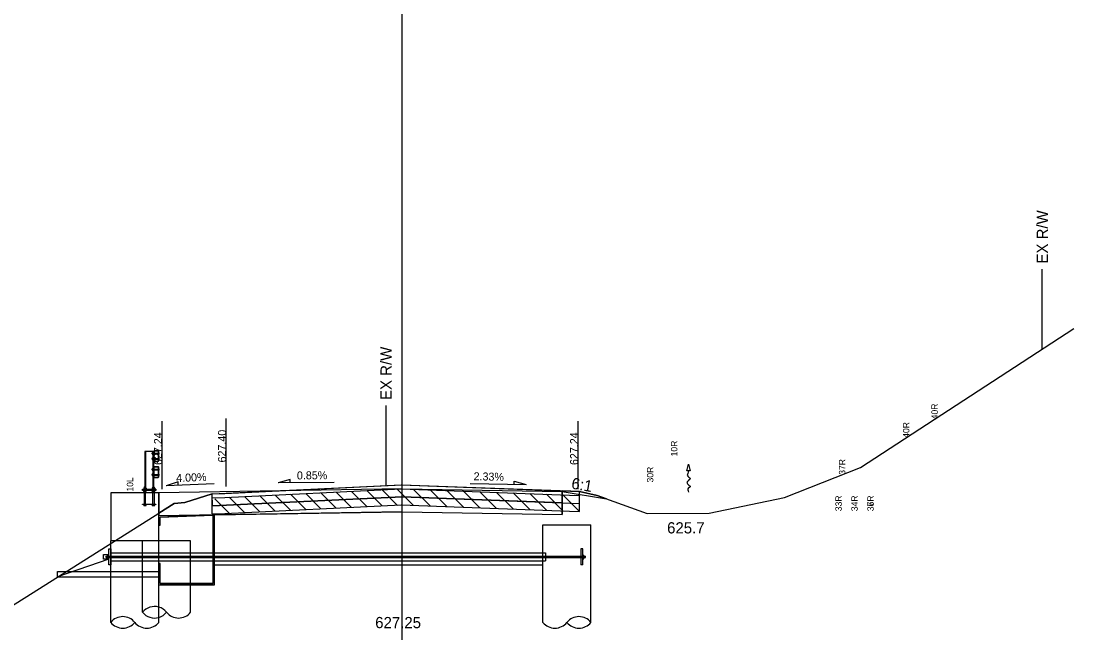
# Model space of a CAD drawing. Extents: x 1866342 to 1870084, y 421982 to 426629.
# Drawn here: x 1866444.3 to 1866510.1, y 426516.9 to 426555.1 of the extents above; entities that cross this region are included whole.
import ezdxf

# ---------------------------------------------------------------- set-up
doc = ezdxf.new("R2010")
doc.units = 0
for name, color, linetype in [('BR_P_Det_Object', 7, 'Continuous'), ('BR_P_Drain_Object', 7, 'Continuous'), ('BR_P_Gen_Hatch', 7, 'Continuous'), ('BR_P_Gen_Porous_Backfill', 7, 'Continuous'), ('BR_P_Sub_Deep_Hidden', 7, 'Continuous'), ('BR_P_Sub_Deep_Object', 7, 'Continuous'), ('BR_P_Sub_Object', 7, 'Continuous'), ('DR_P_Flow_Arrow', 7, 'Continuous'), ('GK_Cells', 7, 'Continuous'), ('RW_X_Fee_RW', 7, 'Continuous'), ('ST_Details', 7, 'Continuous'), ('XS_P_Annotation', 7, 'Continuous'), ('XS_P_Earthwork_Shapes', 7, 'Continuous'), ('XS_P_Finished_Grade', 7, 'Continuous'), ('XS_P_Pavt_Surface', 7, 'Continuous'), ('XS_P_Subgrade', 7, 'Continuous'), ('XS_P_Text_Info', 7, 'Continuous'), ('XS_P_Text_MarkedPoint', 7, 'Continuous'), ('XS_X_Ground_Line', 7, 'Continuous'), ('XS_X_Pavt', 7, 'Continuous')]:
    doc.layers.add(name, color=color, linetype=linetype)

msp = doc.modelspace()

# ---------------------------------------------------------------- linework, layer by layer
at = {"layer": 'BR_P_Det_Object'}
for p, q in [((1866449.46, 426521.491), (1866449.46, 426521.789)), ((1866449.46, 426521.789), (1866449.794, 426521.789)), ((1866449.794, 426521.141), (1866449.794, 426522.141)), ((1866449.794, 426522.141), (1866449.919, 426522.141)), ((1866449.919, 426522.141), (1866449.919, 426521.141)), ((1866449.919, 426521.891), (1866452.919, 426521.891)), ((1866479.294, 426522.141), (1866479.294, 426521.141)), ((1866479.419, 426522.141), (1866479.294, 426522.141)), ((1866479.419, 426521.141), (1866479.419, 426522.141)), ((1866449.794, 426521.491), (1866449.46, 426521.491)), ((1866449.627, 426521.683), (1866479.585, 426521.683)), ((1866449.627, 426521.6), (1866449.627, 426521.683)), ((1866449.627, 426521.6), (1866479.585, 426521.6)), ((1866449.794, 426521.735), (1866449.73, 426521.735)), ((1866449.73, 426521.547), (1866449.73, 426521.735)), ((1866449.794, 426521.547), (1866449.73, 426521.547)), ((1866449.919, 426521.141), (1866449.794, 426521.141)), ((1866449.919, 426521.391), (1866452.919, 426521.391)), ((1866479.419, 426521.141), (1866479.294, 426521.141)), ((1866479.419, 426521.756), (1866479.482, 426521.756)), ((1866479.419, 426521.526), (1866479.482, 426521.526)), ((1866479.482, 426521.526), (1866479.482, 426521.756)), ((1866479.585, 426521.6), (1866479.585, 426521.683))]:
    msp.add_line(p, q, dxfattribs=at)
at = {"layer": 'BR_P_Drain_Object'}
for p, q in [((1866452.919, 426521.891), (1866477.085, 426521.891)), ((1866477.085, 426521.891), (1866477.085, 426521.391)), ((1866452.919, 426521.391), (1866477.085, 426521.391)), ((1866446.597, 426520.725), (1866452.919, 426520.725)), ((1866446.597, 426520.391), (1866446.597, 426520.725)), ((1866446.597, 426520.391), (1866452.919, 426520.391))]:
    msp.add_line(p, q, dxfattribs=at)
at = {"layer": 'BR_P_Gen_Hatch'}
msp.add_lwpolyline([(1866452.919, 426523.624), (1866453.002, 426523.624), (1866453.002, 426524.124), (1866456.319, 426524.247), (1866456.319, 426519.975), (1866453.002, 426519.975), (1866453.002, 426521.225), (1866452.919, 426521.225)], close=True, dxfattribs=at)
at = {"layer": 'BR_P_Gen_Porous_Backfill'}
for p, q in [((1866453.002, 426524.124), (1866455.919, 426524.24)), ((1866453.002, 426523.624), (1866453.002, 426524.124)), ((1866456.319, 426524.247), (1866455.919, 426524.24)), ((1866456.319, 426519.975), (1866456.319, 426524.247)), ((1866453.002, 426523.624), (1866452.919, 426523.624)), ((1866453.002, 426521.225), (1866452.919, 426521.225)), ((1866453.002, 426519.975), (1866453.002, 426521.225)), ((1866453.002, 426519.975), (1866456.319, 426519.975))]:
    msp.add_line(p, q, dxfattribs=at)
at = {"layer": 'BR_P_Sub_Deep_Hidden'}
msp.add_line((1866454.903, 426522.641), (1866452.919, 426522.641), dxfattribs=at)
for points in [[(1866451.903, 426518.178), (1866451.903, 426522.641)], [(1866454.903, 426519.891), (1866454.903, 426522.641)]]:
    msp.add_lwpolyline(points, dxfattribs=at)
for centre, major_axis, start_param, end_param in [((1866452.653, 426517.575), (0.908, 0.32), 0.952163, 2.125879), ((1866452.653, 426518.781), (0.908, -0.32), 4.157306, 5.331022)]:
    msp.add_ellipse(centre, major_axis=major_axis, ratio=0.999997, start_param=start_param, end_param=end_param, dxfattribs=at)
at = {"layer": 'BR_P_Sub_Deep_Object'}
msp.add_line((1866476.919, 426523.641), (1866479.919, 426523.641), dxfattribs=at)
for points in [[(1866476.919, 426517.545), (1866476.919, 426523.641)], [(1866479.919, 426517.545), (1866479.919, 426523.641)], [(1866449.919, 426517.545), (1866449.919, 426522.641)], [(1866452.919, 426517.545), (1866452.919, 426522.641)], [(1866454.903, 426518.178), (1866454.903, 426519.891)]]:
    msp.add_lwpolyline(points, dxfattribs=at)
for centre, major_axis, start_param, end_param in [((1866452.653, 426517.575), (0.908, 0.32), 0.338571, 0.952163), ((1866450.669, 426516.942), (0.908, 0.32), 0.338571, 2.125879), ((1866452.653, 426518.781), (0.908, -0.32), 5.331022, 5.944615), ((1866454.153, 426518.781), (0.908, 0.32), 3.480163, 5.267472), ((1866479.169, 426516.942), (-0.908, 0.32), 4.157306, 5.944615), ((1866450.669, 426518.148), (0.908, -0.32), 4.157306, 5.944615), ((1866452.169, 426518.148), (0.908, 0.32), 3.480163, 5.267472), ((1866477.669, 426518.148), (-0.908, 0.32), 1.015713, 2.803022), ((1866479.169, 426518.148), (-0.908, -0.32), 0.33857, 2.125879)]:
    msp.add_ellipse(centre, major_axis=major_axis, ratio=0.999997, start_param=start_param, end_param=end_param, dxfattribs=at)
at = {"layer": 'BR_P_Sub_Object'}
for p, q in [((1866452.919, 426525.641), (1866449.919, 426525.641)), ((1866449.919, 426525.641), (1866449.919, 426522.641)), ((1866452.919, 426522.641), (1866452.919, 426525.641))]:
    msp.add_line(p, q, dxfattribs=at)
msp.add_lwpolyline([(1866452.919, 426522.641), (1866449.919, 426522.641)], dxfattribs=at)
at = {"layer": 'DR_P_Flow_Arrow'}
for p, q in [((1866485.905, 426527.024), (1866486.013, 426527.424)), ((1866486.013, 426527.424), (1866486.12, 426527.024)), ((1866486.12, 426527.024), (1866485.905, 426527.024))]:
    msp.add_line(p, q, dxfattribs=at)
msp.add_spline([(1866486.011, 426527.025), (1866486.011, 426527.009), (1866485.974, 426526.844), (1866485.938, 426526.74), (1866486.121, 426526.528), (1866485.915, 426526.285), (1866486.121, 426526.005), (1866486.01, 426525.949), (1866486.013, 426525.674)], degree=3, dxfattribs=at)
at = {"layer": 'GK_Cells'}
msp.add_line((1866468.119, 426490.634), (1866468.119, 426626.453), dxfattribs=at)
at = {"layer": 'RW_X_Fee_RW'}
for p, q in [((1866508.119, 426534.617), (1866508.119, 426539.617)), ((1866467.119, 426526.093), (1866467.119, 426531.093))]:
    msp.add_line(p, q, dxfattribs=at)
at = {"layer": 'ST_Details'}
for p, q in [((1866452.054, 426528.224), (1866452.054, 426526.006)), ((1866452.585, 426528.224), (1866452.054, 426528.224)), ((1866452.092, 426528.224), (1866452.092, 426526)), ((1866452.501, 426528.125), (1866452.485, 426528.125)), ((1866452.485, 426528.125), (1866452.485, 426528.073)), ((1866452.501, 426528.073), (1866452.485, 426528.073)), ((1866452.501, 426527.792), (1866452.485, 426527.792)), ((1866452.485, 426527.792), (1866452.485, 426527.74)), ((1866452.501, 426527.74), (1866452.485, 426527.74)), ((1866452.501, 426528.133), (1866452.501, 426528.066)), ((1866452.501, 426527.799), (1866452.501, 426527.733)), ((1866452.51, 426528.077), (1866452.547, 426528.077)), ((1866452.51, 426527.744), (1866452.547, 426527.744)), ((1866452.547, 426528.144), (1866452.511, 426528.144)), ((1866452.511, 426528.122), (1866452.547, 426528.122)), ((1866452.511, 426528.055), (1866452.547, 426528.055)), ((1866452.547, 426527.81), (1866452.511, 426527.81)), ((1866452.511, 426527.788), (1866452.547, 426527.788)), ((1866452.511, 426527.722), (1866452.547, 426527.722)), ((1866452.547, 426528.224), (1866452.547, 426526)), ((1866452.547, 426528.055), (1866452.547, 426528.144)), ((1866452.547, 426527.722), (1866452.547, 426527.81)), ((1866452.585, 426528.224), (1866452.585, 426526.006)), ((1866452.585, 426528.214), (1866452.585, 426527.652)), ((1866452.611, 426528.214), (1866452.611, 426527.652)), ((1866452.611, 426528.125), (1866452.893, 426528.125)), ((1866452.611, 426528.073), (1866452.893, 426528.073)), ((1866452.611, 426527.792), (1866452.893, 426527.792)), ((1866452.611, 426527.74), (1866452.893, 426527.74)), ((1866452.867, 426528.266), (1866452.637, 426528.266)), ((1866452.867, 426528.24), (1866452.637, 426528.24)), ((1866452.893, 426527.652), (1866452.893, 426528.214)), ((1866452.919, 426527.652), (1866452.919, 426528.214)), ((1866452.501, 426527.125), (1866452.485, 426527.125)), ((1866452.485, 426527.125), (1866452.485, 426527.073)), ((1866452.501, 426527.073), (1866452.485, 426527.073)), ((1866452.501, 426527.133), (1866452.501, 426527.066)), ((1866452.51, 426527.077), (1866452.547, 426527.077)), ((1866452.547, 426527.144), (1866452.511, 426527.144)), ((1866452.511, 426527.122), (1866452.547, 426527.122)), ((1866452.511, 426527.055), (1866452.547, 426527.055)), ((1866452.547, 426527.055), (1866452.547, 426527.144)), ((1866452.585, 426527.235), (1866452.585, 426526.631)), ((1866452.611, 426527.214), (1866452.611, 426526.652)), ((1866452.611, 426527.125), (1866452.893, 426527.125)), ((1866452.611, 426527.073), (1866452.893, 426527.073)), ((1866452.887, 426527.266), (1866452.617, 426527.266)), ((1866452.637, 426527.626), (1866452.867, 426527.626)), ((1866452.637, 426527.599), (1866452.867, 426527.599)), ((1866452.867, 426527.24), (1866452.637, 426527.24)), ((1866452.893, 426526.652), (1866452.893, 426527.214)), ((1866452.919, 426526.631), (1866452.919, 426527.235)), ((1866452.501, 426526.792), (1866452.485, 426526.792)), ((1866452.485, 426526.792), (1866452.485, 426526.74)), ((1866452.501, 426526.74), (1866452.485, 426526.74)), ((1866452.501, 426526.799), (1866452.501, 426526.733)), ((1866452.51, 426526.744), (1866452.547, 426526.744)), ((1866452.547, 426526.81), (1866452.511, 426526.81)), ((1866452.511, 426526.788), (1866452.547, 426526.788)), ((1866452.511, 426526.722), (1866452.547, 426526.722)), ((1866452.547, 426526.722), (1866452.547, 426526.81)), ((1866452.611, 426526.792), (1866452.893, 426526.792)), ((1866452.611, 426526.74), (1866452.893, 426526.74)), ((1866452.617, 426526.599), (1866452.887, 426526.599)), ((1866452.637, 426526.626), (1866452.867, 426526.626)), ((1866451.971, 426525.875), (1866452.137, 426525.875)), ((1866451.971, 426525.86), (1866451.971, 426525.875)), ((1866452.137, 426525.86), (1866451.971, 426525.86)), ((1866451.971, 426525.777), (1866452.137, 426525.777)), ((1866451.971, 426525.762), (1866451.971, 426525.777)), ((1866452.137, 426525.762), (1866451.971, 426525.762)), ((1866451.976, 426525.941), (1866451.976, 426525.875)), ((1866452.132, 426525.875), (1866451.976, 426525.875)), ((1866451.976, 426525.732), (1866451.976, 426525.762)), ((1866451.995, 426525.957), (1866452.112, 426525.957)), ((1866452.012, 426525.996), (1866452.023, 426526.006)), ((1866452.012, 426525.996), (1866452.096, 426525.996)), ((1866452.012, 426525.996), (1866452.012, 426525.957)), ((1866452.012, 426525.985), (1866452.096, 426525.985)), ((1866452.012, 426525.975), (1866452.096, 426525.975)), ((1866452.012, 426525.964), (1866452.096, 426525.964)), ((1866452.012, 426525.86), (1866452.012, 426525.777)), ((1866452.015, 426525.941), (1866452.015, 426525.875)), ((1866452.015, 426525.732), (1866452.015, 426525.762)), ((1866452.085, 426526.006), (1866452.023, 426526.006)), ((1866452.085, 426526.006), (1866452.096, 426525.996)), ((1866452.093, 426525.941), (1866452.093, 426525.875)), ((1866452.093, 426525.732), (1866452.093, 426525.762)), ((1866452.096, 426525.957), (1866452.096, 426525.996)), ((1866452.096, 426525.777), (1866452.096, 426525.86)), ((1866452.132, 426525.941), (1866452.132, 426525.875)), ((1866452.132, 426525.732), (1866452.132, 426525.762)), ((1866452.137, 426525.875), (1866452.137, 426525.86)), ((1866452.137, 426525.777), (1866452.137, 426525.762)), ((1866452.668, 426525.875), (1866452.502, 426525.875)), ((1866452.502, 426525.875), (1866452.502, 426525.86)), ((1866452.502, 426525.86), (1866452.668, 426525.86)), ((1866452.502, 426525.777), (1866452.668, 426525.777)), ((1866452.502, 426525.762), (1866452.502, 426525.777)), ((1866452.668, 426525.762), (1866452.502, 426525.762)), ((1866452.507, 426525.941), (1866452.507, 426525.875)), ((1866452.507, 426525.875), (1866452.663, 426525.875)), ((1866452.507, 426525.732), (1866452.507, 426525.762)), ((1866452.644, 426525.957), (1866452.526, 426525.957)), ((1866452.554, 426526.006), (1866452.543, 426525.996)), ((1866452.627, 426525.996), (1866452.543, 426525.996)), ((1866452.543, 426525.957), (1866452.543, 426525.996)), ((1866452.627, 426525.985), (1866452.543, 426525.985)), ((1866452.627, 426525.975), (1866452.543, 426525.975)), ((1866452.627, 426525.964), (1866452.543, 426525.964)), ((1866452.543, 426525.777), (1866452.543, 426525.86)), ((1866452.546, 426525.941), (1866452.546, 426525.875)), ((1866452.546, 426525.732), (1866452.546, 426525.762)), ((1866452.554, 426526.006), (1866452.616, 426526.006)), ((1866452.627, 426525.996), (1866452.616, 426526.006)), ((1866452.624, 426525.941), (1866452.624, 426525.875)), ((1866452.624, 426525.732), (1866452.624, 426525.762)), ((1866452.627, 426525.996), (1866452.627, 426525.957)), ((1866452.627, 426525.86), (1866452.627, 426525.777)), ((1866452.663, 426525.941), (1866452.663, 426525.875)), ((1866452.663, 426525.732), (1866452.663, 426525.762)), ((1866452.668, 426525.86), (1866452.668, 426525.875)), ((1866452.668, 426525.777), (1866452.668, 426525.762)), ((1866451.995, 426525.716), (1866452.112, 426525.716)), ((1866452.012, 426525.652), (1866452.012, 426525.716)), ((1866452.012, 426525.652), (1866452.012, 426524.933)), ((1866452.096, 426525.652), (1866452.096, 426525.716)), ((1866452.096, 426524.933), (1866452.096, 426525.652)), ((1866452.526, 426525.716), (1866452.644, 426525.716)), ((1866452.543, 426525.652), (1866452.543, 426525.716)), ((1866452.543, 426524.933), (1866452.543, 426525.652)), ((1866452.627, 426525.652), (1866452.627, 426525.716)), ((1866452.627, 426525.652), (1866452.627, 426524.933)), ((1866451.976, 426524.867), (1866451.976, 426524.902)), ((1866451.995, 426524.851), (1866452.112, 426524.851)), ((1866452.015, 426524.867), (1866452.015, 426524.902)), ((1866452.093, 426524.867), (1866452.093, 426524.902)), ((1866452.132, 426524.867), (1866452.132, 426524.902)), ((1866452.507, 426524.867), (1866452.507, 426524.902)), ((1866452.644, 426524.851), (1866452.526, 426524.851)), ((1866452.546, 426524.867), (1866452.546, 426524.902)), ((1866452.624, 426524.867), (1866452.624, 426524.902)), ((1866452.663, 426524.867), (1866452.663, 426524.902))]:
    msp.add_line(p, q, dxfattribs=at)
for points in [[(1866451.903, 426525.86), (1866452.736, 426525.86), (1866452.736, 426525.777), (1866451.903, 426525.777)], [(1866451.903, 426524.933), (1866452.736, 426524.933), (1866452.736, 426524.902), (1866451.903, 426524.902)]]:
    msp.add_lwpolyline(points, close=True, dxfattribs=at)
for centre, radius, start, end in [((1866452.637, 426528.214), 0.0521, 90, 180), ((1866452.637, 426528.214), 0.026, 90, 180), ((1866452.867, 426528.214), 0.0521, 0, 90), ((1866452.867, 426528.214), 0.026, 0, 90), ((1866452.891, 426528.099), 0.0558, 300, 60), ((1866452.891, 426527.766), 0.0558, 300, 60), ((1866452.637, 426527.652), 0.0521, 180, 270), ((1866452.617, 426527.235), 0.0312, 90, 180), ((1866452.637, 426527.652), 0.026, 180, 270), ((1866452.637, 426527.214), 0.026, 90, 180), ((1866452.867, 426527.652), 0.0521, 270, 0), ((1866452.867, 426527.652), 0.026, 270, 0), ((1866452.867, 426527.214), 0.026, 0, 90), ((1866452.887, 426527.235), 0.0312, 0, 90), ((1866452.891, 426527.099), 0.0558, 300, 60), ((1866452.617, 426526.631), 0.0312, 180, 270), ((1866452.637, 426526.652), 0.026, 180, 270), ((1866452.867, 426526.652), 0.026, 270, 0), ((1866452.887, 426526.631), 0.0312, 270, 0), ((1866452.891, 426526.766), 0.0558, 300, 60)]:
    msp.add_arc(centre, radius, start, end, dxfattribs=at)
for centre, major_axis, ratio, start_param, end_param in [((1866452.511, 426528.133), (0, -0.0111), 0.939759, 3.141593, 6.283185), ((1866452.511, 426528.099), (0, -0.0222), 0.469173, 3.141593, 6.283185), ((1866452.511, 426528.066), (0, 0.0111), 0.939759, 0, 3.141593), ((1866452.511, 426527.799), (0, -0.0111), 0.939759, 3.141593, 6.283185), ((1866452.511, 426527.766), (0, -0.0222), 0.469173, 3.141593, 6.283185), ((1866452.511, 426527.733), (0, 0.0111), 0.939759, 0, 3.141593), ((1866452.511, 426527.133), (0, -0.0111), 0.939759, 3.141593, 6.283185), ((1866452.511, 426527.099), (0, -0.0222), 0.469173, 3.141593, 6.283185), ((1866452.511, 426527.066), (0, 0.0111), 0.939759, 0, 3.141593), ((1866452.511, 426526.799), (0, -0.0111), 0.939759, 3.141593, 6.283185), ((1866452.511, 426526.766), (0, -0.0222), 0.469173, 3.141593, 6.283185), ((1866452.511, 426526.733), (0, 0.0111), 0.939759, 0, 3.141593), ((1866451.995, 426525.941), (0.0195, 0), 0.798056, 0, 3.141593), ((1866451.995, 426525.732), (0.0195, 0), 0.798056, 3.141593, 6.283185), ((1866452.054, 426525.941), (0.0391, 0), 0.399304, 0, 3.141593), ((1866452.054, 426525.732), (0.0391, 0), 0.399304, 3.141593, 6.283185), ((1866452.112, 426525.941), (0.0195, 0), 0.798056, 0, 3.141593), ((1866452.112, 426525.732), (0.0195, 0), 0.798056, 3.141593, 6.283185), ((1866452.526, 426525.941), (-0.0195, 0), 0.798056, 3.141593, 6.283185), ((1866452.526, 426525.732), (0.0195, 0), 0.798056, 3.141593, 6.283185), ((1866452.585, 426525.941), (-0.0391, 0), 0.399304, 3.141593, 6.283185), ((1866452.585, 426525.732), (0.0391, 0), 0.399304, 3.141593, 6.283185), ((1866452.644, 426525.941), (-0.0195, 0), 0.798056, 3.141593, 6.283185), ((1866452.644, 426525.732), (0.0195, 0), 0.798056, 3.141593, 6.283185), ((1866451.995, 426524.867), (0.0195, 0), 0.798056, 3.141593, 6.283185), ((1866452.054, 426524.867), (0.0391, 0), 0.399304, 3.141593, 6.283185), ((1866452.112, 426524.867), (0.0195, 0), 0.798056, 3.141593, 6.283185), ((1866452.526, 426524.867), (-0.0195, 0), 0.798056, 0, 3.141593), ((1866452.585, 426524.867), (-0.0391, 0), 0.399304, 0, 3.141593), ((1866452.644, 426524.867), (-0.0195, 0), 0.798056, 0, 3.141593)]:
    msp.add_ellipse(centre, major_axis=major_axis, ratio=ratio, start_param=start_param, end_param=end_param, dxfattribs=at)
at = {"layer": 'XS_P_Annotation'}
for q in [(1866452.919, 426525.641), (1866478.119, 426525.724)]:
    msp.add_line((1866468.119, 426525.884), q, dxfattribs=at)
at = {"layer": 'XS_P_Earthwork_Shapes'}
for p, q in [((1866478.119, 426524.287), (1866478.119, 426525.724)), ((1866478.119, 426525.724), (1866480.89, 426525.262)), ((1866468.119, 426524.447), (1866478.119, 426524.287)), ((1866452.919, 426524.368), (1866452.919, 426524.204))]:
    msp.add_line(p, q, dxfattribs=at)
for points in [[(1866452.919, 426524.368), (1866453.872, 426524.967), (1866454.539, 426525.044), (1866456.248, 426525.574), (1866468.119, 426526.136)], [(1866480.89, 426525.262), (1866480.309, 426525.474), (1866479.212, 426525.73), (1866478.119, 426525.77), (1866478.119, 426525.019), (1866468.119, 426525.381), (1866456.283, 426524.825), (1866456.248, 426525.574), (1866454.539, 426525.044), (1866453.872, 426524.967), (1866452.919, 426524.368)], [(1866456.248, 426525.574), (1866468.119, 426526.132), (1866479.212, 426525.73)], [(1866456.283, 426524.825), (1866468.123, 426525.381), (1866479.185, 426524.981)], [(1866452.919, 426524.204), (1866456.403, 426524.259), (1866468.119, 426524.447)]]:
    msp.add_lwpolyline(points, dxfattribs=at)
at = {"layer": 'XS_P_Finished_Grade'}
for p, q in [((1866478.119, 426525.724), (1866480.89, 426525.262)), ((1866449.794, 426521.491), (1866446.597, 426520.391))]:
    msp.add_line(p, q, dxfattribs=at)
at = {"layer": 'XS_P_Pavt_Surface'}
for p, q in [((1866458.064, 426525.653), (1866468.064, 426526.134)), ((1866468.064, 426526.134), (1866479.212, 426525.73))]:
    msp.add_line(p, q, dxfattribs=at)
at = {"layer": 'XS_P_Subgrade'}
for p, q in [((1866478.119, 426525.724), (1866478.119, 426524.287)), ((1866452.919, 426525.641), (1866452.919, 426524.204)), ((1866452.919, 426525.641), (1866452.919, 426524.204)), ((1866468.119, 426524.447), (1866452.919, 426524.204)), ((1866468.119, 426524.447), (1866478.119, 426524.287)), ((1866456.403, 426519.891), (1866456.403, 426524.324)), ((1866456.403, 426521.141), (1866476.919, 426521.141)), ((1866452.919, 426519.891), (1866456.403, 426519.891))]:
    msp.add_line(p, q, dxfattribs=at)
at = {"layer": 'XS_P_Text_Info'}
for p, q in [((1866453.119, 426525.878), (1866453.119, 426530.128)), ((1866457.119, 426526.038), (1866457.119, 426530.288)), ((1866479.119, 426525.876), (1866479.119, 426530.126)), ((1866461.119, 426526.472), (1866460.369, 426526.266)), ((1866461.119, 426526.272), (1866461.119, 426526.472)), ((1866454.119, 426526.318), (1866453.369, 426526.088)), ((1866456.369, 426526.208), (1866453.369, 426526.088)), ((1866454.119, 426526.118), (1866454.119, 426526.318)), ((1866463.869, 426526.296), (1866460.369, 426526.266)), ((1866472.369, 426526.233), (1866475.869, 426526.151)), ((1866475.119, 426526.369), (1866475.869, 426526.151)), ((1866475.119, 426526.169), (1866475.119, 426526.369))]:
    msp.add_line(p, q, dxfattribs=at)
at = {"layer": 'XS_X_Ground_Line'}
msp.add_line((1866449.919, 426525.641), (1866449.919, 426523.641), dxfattribs=at)
msp.add_lwpolyline([(1866442.343, 426517.715), (1866453.872, 426524.967), (1866454.539, 426525.044), (1866456.248, 426525.574), (1866457.047, 426525.604), (1866468.064, 426526.134), (1866478.57, 426525.755), (1866479.212, 426525.73), (1866480.309, 426525.474), (1866483.425, 426524.34), (1866487.314, 426524.376), (1866492.011, 426525.342), (1866496.773, 426527.227), (1866510.1, 426535.907)], dxfattribs=at)
at = {"layer": 'XS_X_Pavt'}
for p, q in [((1866457.047, 426525.354), (1866468.064, 426525.884)), ((1866465.915, 426524.778), (1866464.959, 426525.733)), ((1866466.874, 426524.819), (1866465.915, 426525.778)), ((1866467.841, 426524.851), (1866466.874, 426525.819)), ((1866468.837, 426524.856), (1866467.841, 426525.851)), ((1866468.064, 426525.884), (1866478.57, 426525.505)), ((1866469.874, 426524.819), (1866468.837, 426525.856)), ((1866470.911, 426524.781), (1866469.874, 426525.819)), ((1866471.949, 426524.744), (1866470.911, 426525.781)), ((1866472.986, 426524.706), (1866471.949, 426525.744)), ((1866479.212, 426525.48), (1866479.212, 426525.73)), ((1866456.248, 426525.324), (1866456.248, 426525.574)), ((1866456.248, 426525.324), (1866457.047, 426525.354)), ((1866456.248, 426524.324), (1866456.248, 426525.324)), ((1866457.323, 426524.369), (1866456.429, 426525.264)), ((1866458.279, 426524.414), (1866457.323, 426525.369)), ((1866459.233, 426524.459), (1866458.279, 426525.414)), ((1866460.187, 426524.505), (1866459.233, 426525.459)), ((1866461.141, 426524.551), (1866460.187, 426525.505)), ((1866462.096, 426524.597), (1866461.141, 426525.551)), ((1866463.05, 426524.643), (1866462.096, 426525.597)), ((1866464.004, 426524.688), (1866463.05, 426525.643)), ((1866464.959, 426524.733), (1866464.004, 426525.688)), ((1866474.023, 426524.669), (1866472.986, 426525.706)), ((1866475.061, 426524.632), (1866474.023, 426525.669)), ((1866476.098, 426524.594), (1866475.061, 426525.632)), ((1866477.136, 426524.557), (1866476.098, 426525.594)), ((1866478.173, 426524.519), (1866477.136, 426525.557)), ((1866479.212, 426524.48), (1866478.173, 426525.519)), ((1866478.57, 426525.505), (1866479.212, 426525.48)), ((1866479.212, 426524.48), (1866479.212, 426525.48)), ((1866457.047, 426524.354), (1866468.064, 426524.884)), ((1866468.064, 426524.884), (1866478.57, 426524.505)), ((1866478.57, 426524.505), (1866479.212, 426524.48)), ((1866456.248, 426524.324), (1866457.047, 426524.354))]:
    msp.add_line(p, q, dxfattribs=at)

# ---------------------------------------------------------------- texts
at = {"layer": 'RW_X_Fee_RW'}
for p in [(1866508.469, 426539.967), (1866467.469, 426531.443)]:
    msp.add_text('EX R/W', height=0.7, rotation=90, dxfattribs=at).set_placement(p)
at = {"layer": 'XS_P_Annotation'}
msp.add_text('6:1', height=0.7, rotation=349.95478, dxfattribs=at).set_placement((1866478.659, 426525.913))
for s, p in [('625.7', (1866484.68, 426523.104)), ('627.25', (1866466.44, 426517.184))]:
    msp.add_text(s, height=0.7, dxfattribs=at).set_placement(p)
at = {"layer": 'XS_P_Text_Info'}
for s, rotation, p in [('627.24', 90, (1866453.119, 426527.378)), ('627.40', 90, (1866457.119, 426527.538)), ('627.24', 90, (1866479.119, 426527.376)), ('4.00%', 2.29061, (1866454.013, 426526.314)), ('0.85%', 0.48641, (1866461.55, 426526.476)), ('2.33%', 358.66584, (1866472.583, 426526.428))]:
    msp.add_text(s, height=0.5, rotation=rotation, dxfattribs=at).set_placement(p)
at = {"layer": 'XS_P_Text_MarkedPoint'}
for s, p in [('40R', (1866501.592, 426530.236)), ('40R', (1866499.814, 426529.078)), ('10R', (1866485.319, 426527.918)), ('37R', (1866495.814, 426526.769)), ('30R', (1866483.819, 426526.289)), ('10L', (1866451.319, 426525.718)), ('33R', (1866495.592, 426524.494)), ('34R', (1866496.592, 426524.494)), ('35R', (1866497.592, 426524.494)), ('36R', (1866497.592, 426524.494)), ('37R', (1866497.592, 426524.494))]:
    msp.add_text(s, height=0.4, rotation=90, dxfattribs=at).set_placement(p)

doc.saveas('drawing.dxf')
